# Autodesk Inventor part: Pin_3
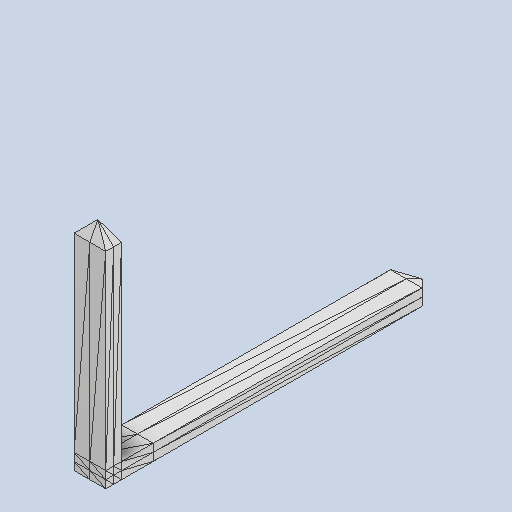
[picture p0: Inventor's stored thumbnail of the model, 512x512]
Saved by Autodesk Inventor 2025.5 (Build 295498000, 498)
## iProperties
Created: 2026-10
Part Number: Pin_3
Material: Genérico
Document SubType Name: Modeling
Designer: Luis M
Density: 1 g/cm^3
Appearance: Valor por defecto
Author: Luis M
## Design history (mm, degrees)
feature "Base1"
node "Sólido1"
